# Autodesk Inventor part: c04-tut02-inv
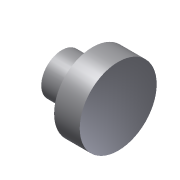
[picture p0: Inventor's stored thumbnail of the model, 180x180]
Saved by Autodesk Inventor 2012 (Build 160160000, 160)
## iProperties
Created: 2010-01
Part Number: c04-tut02-inv
Document SubType Name: Modeling
Designer: CADSoft
Density: 1 g/cm^3
Material: Default
Author: CADSoft
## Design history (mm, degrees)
sketch "Sketch1"
  geometry: L1 (22, 0)-(22, 30); L2 (22, 30)-(2, 30); L3 (2, 30)-(2, 25); L4 (2, 25)-(15.5, 25); L5 (17, 23.5)-(17, 17.5); L6 (15.5, 16)-(-22, 16); L7 (-22, 16)-(-22, 10); L8 (-22, 10)-(-15.5, 10); L9 (-14, 8.5)-(-14, 4); L10 (-14, 4)-(0, 4); L11 (0, 4)-(0, 0); L12 (0, 0)-(22, 0); A1 r 1.5 centre (-15.5, 8.5) between (-14, 8.5) and (-15.5, 10); A2 r 1.5 centre (15.5, 23.5) between (17, 23.5) and (15.5, 25); A3 r 1.5 centre (15.5, 17.5) between (15.5, 16) and (17, 17.5); 2 further points
  constraints: 24 end point, 6 point on circle, 6 tangent, 3 centre point, 2 coincident, 2 equal radius, 2 vertical, 1 horizontal, 1 other
  dimensions: "d0" = 8 diameter of L10 L12; "d1" = 20 diameter of L8 L12; "d2" = 32 diameter of L6 L12; "d3" = 50 diameter of L4 L12; "d5" = 60 diameter of L2 L12; "d6" = 5 distance between parallel lines of L5 L1; "d7" = 20 distance of L1.end L2.end; "d8" = 22 distance of L11.end L1.start; "d9" = 36 distance between parallel lines of L9 L1; "d10" = 44 distance between parallel lines of L7 L1; "d11" = 1.5 radius of A1
revolve "Revolution1" sketch "Sketch1" stored, may be unused: angle "d12" = 90 deg
body "Solid1"
